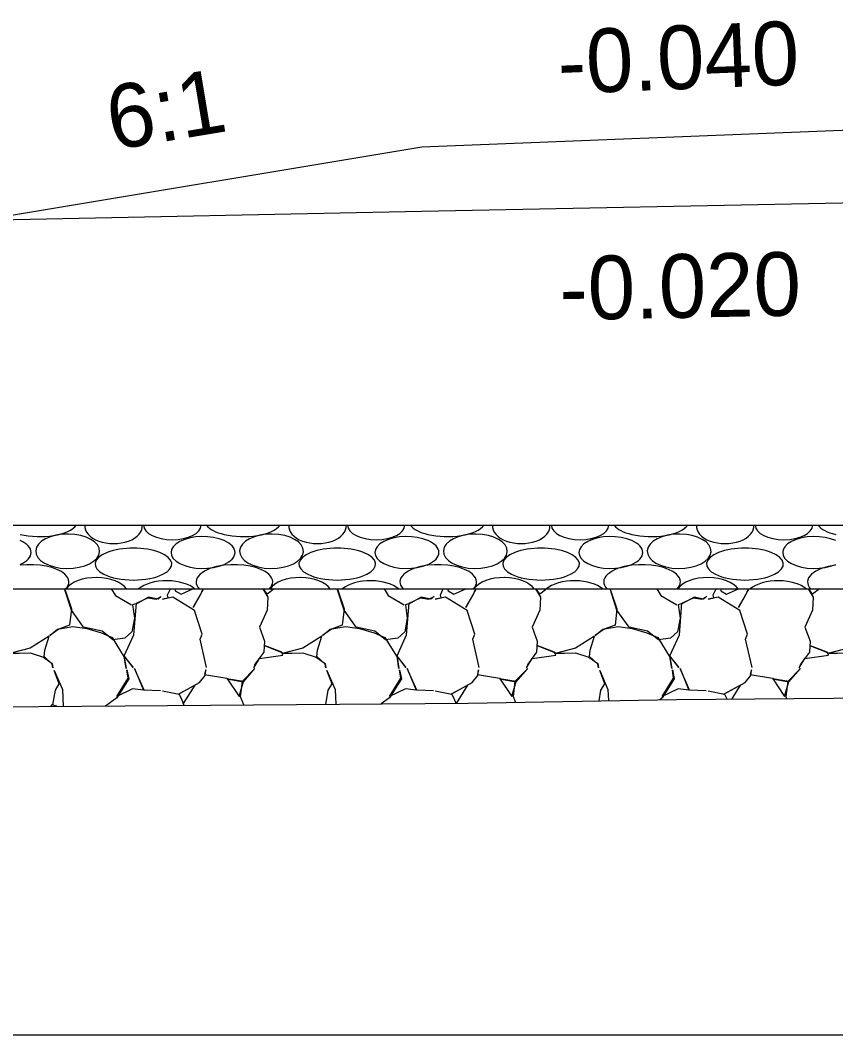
# Model space of a CAD drawing. Extents: x -26 to 4781, y -31 to 24738.
# Drawn here: x 2271.7 to 2284.49, y 14500 to 14515.93 of the extents above; entities that cross this region are included whole.
import ezdxf

# ---------------------------------------------------------------- set-up
doc = ezdxf.new("R2010")
doc.units = 0
for name, color, linetype in [('DESIGN - SHEET - Light Grid', 7, 'Continuous'), ('DESIGN - TRANSPORTATION - Proposed Layout Patterning', 7, 'Continuous'), ('DESIGN - TYPICAL - Finished Grade and Subgrade', 7, 'Continuous'), ('DESIGN - TYPICAL - Finished Grade Slopes Text', 7, 'Continuous'), ('DESIGN - TYPICAL - Subgrade Cross Slope Text', 7, 'Continuous'), ('GEOTECHNICAL – SCRATCH – Level 1', 7, 'Continuous'), ('SURVEY - GROUND - Top of Ground', 7, 'Continuous')]:
    doc.layers.add(name, color=color, linetype=linetype)

msp = doc.modelspace()

# ---------------------------------------------------------------- linework, layer by layer
at = {"layer": 'DESIGN - SHEET - Light Grid'}
msp.add_line((2000, 14500), (2300, 14500), dxfattribs=at)
at = {"layer": 'DESIGN - TRANSPORTATION - Proposed Layout Patterning'}
for points in [[(2271.224, 14507), (2271.301, 14506.869), (2271.291, 14506.669), (2271.171, 14506.399), (2271.251, 14506.179), (2271.241, 14506.009), (2271.101, 14505.819), (2271.081, 14505.759), (2271.171, 14505.909), (2271.541, 14505.959), (2271.521, 14506.009), (2271.261, 14506.109), (2271.551, 14505.989), (2271.681, 14505.989), (2271.851, 14505.999), (2272.061, 14505.929), (2272.201, 14505.829), (2272.211, 14505.759), (2272.201, 14505.819), (2272.071, 14505.939), (2272.081, 14506.039), (2272.151, 14506.259), (2271.851, 14506.069), (2271.551, 14505.989)], [(2272.383, 14507), (2272.401, 14506.979), (2272.501, 14506.689), (2272.471, 14506.429), (2272.301, 14506.369), (2272.161, 14506.269), (2272.281, 14506.369), (2272.521, 14506.409), (2272.741, 14506.379), (2272.971, 14506.309), (2273.141, 14506.239), (2273.331, 14505.929), (2273.361, 14505.749), (2273.331, 14505.939), (2273.471, 14505.769), (2273.331, 14505.949), (2273.481, 14506.279), (2273.521, 14506.779), (2273.701, 14506.859), (2273.831, 14506.839), (2273.911, 14506.879), (2273.861, 14506.839), (2273.711, 14506.869), (2273.541, 14506.779), (2273.461, 14506.749), (2273.491, 14506.539), (2273.451, 14506.329), (2273.341, 14506.229), (2273.151, 14506.199), (2272.981, 14506.339), (2272.691, 14506.399), (2272.501, 14506.669), (2272.393, 14507)], [(2273.127, 14507), (2273.191, 14506.899), (2273.441, 14506.749)], [(2274.621, 14505.769), (2274.521, 14506.209), (2274.551, 14506.289), (2274.431, 14506.659), (2274.091, 14506.869), (2273.931, 14506.839), (2274.021, 14506.859), (2274.011, 14506.909), (2274.056, 14507)], [(2274.125, 14507), (2274.131, 14506.969), (2274.221, 14506.919), (2274.408, 14507)], [(2274.573, 14507), (2274.521, 14506.909), (2274.411, 14506.709), (2274.521, 14506.899), (2274.568, 14507)], [(2275.504, 14507), (2275.581, 14506.869), (2275.571, 14506.669), (2275.451, 14506.399), (2275.531, 14506.179), (2275.521, 14506.009), (2275.381, 14505.819), (2275.361, 14505.759), (2275.451, 14505.909), (2275.821, 14505.959), (2275.801, 14506.009), (2275.541, 14506.109), (2275.831, 14505.989), (2275.961, 14505.989), (2276.131, 14505.999), (2276.341, 14505.929), (2276.481, 14505.829), (2276.491, 14505.759), (2276.481, 14505.819), (2276.351, 14505.939), (2276.361, 14506.039), (2276.431, 14506.259), (2276.131, 14506.069), (2275.831, 14505.989)], [(2275.68, 14507), (2275.571, 14506.919), (2275.515, 14507)], [(2276.663, 14507), (2276.681, 14506.979), (2276.781, 14506.689), (2276.751, 14506.429), (2276.581, 14506.369), (2276.441, 14506.269), (2276.561, 14506.369), (2276.801, 14506.409), (2277.021, 14506.379), (2277.251, 14506.309), (2277.421, 14506.239), (2277.611, 14505.929), (2277.641, 14505.749), (2277.611, 14505.939), (2277.751, 14505.769), (2277.611, 14505.949), (2277.761, 14506.279), (2277.801, 14506.779), (2277.981, 14506.859), (2278.111, 14506.839), (2278.191, 14506.879), (2278.141, 14506.839), (2277.991, 14506.869), (2277.821, 14506.779), (2277.741, 14506.749), (2277.771, 14506.539), (2277.731, 14506.329), (2277.621, 14506.229), (2277.431, 14506.199), (2277.261, 14506.339), (2276.971, 14506.399), (2276.781, 14506.669), (2276.673, 14507)], [(2277.407, 14507), (2277.471, 14506.899), (2277.721, 14506.749)], [(2278.901, 14505.769), (2278.801, 14506.209), (2278.831, 14506.289), (2278.711, 14506.659), (2278.371, 14506.869), (2278.211, 14506.839), (2278.301, 14506.859), (2278.291, 14506.909), (2278.336, 14507)], [(2278.405, 14507), (2278.411, 14506.969), (2278.501, 14506.919), (2278.688, 14507)], [(2278.853, 14507), (2278.801, 14506.909), (2278.691, 14506.709), (2278.801, 14506.899), (2278.848, 14507)], [(2279.784, 14507), (2279.861, 14506.869), (2279.851, 14506.669), (2279.731, 14506.399), (2279.811, 14506.179), (2279.801, 14506.009), (2279.661, 14505.819), (2279.641, 14505.759), (2279.731, 14505.909), (2280.101, 14505.959), (2280.081, 14506.009), (2279.821, 14506.109), (2280.111, 14505.989), (2280.241, 14505.989), (2280.411, 14505.999), (2280.621, 14505.929), (2280.761, 14505.829), (2280.771, 14505.759), (2280.761, 14505.819), (2280.631, 14505.939), (2280.641, 14506.039), (2280.711, 14506.259), (2280.411, 14506.069), (2280.111, 14505.989)], [(2279.96, 14507), (2279.851, 14506.919), (2279.795, 14507)], [(2280.943, 14507), (2280.961, 14506.979), (2281.061, 14506.689), (2281.031, 14506.429), (2280.861, 14506.369), (2280.721, 14506.269), (2280.841, 14506.369), (2281.081, 14506.409), (2281.301, 14506.379), (2281.531, 14506.309), (2281.701, 14506.239), (2281.891, 14505.929), (2281.921, 14505.749), (2281.891, 14505.939), (2282.031, 14505.769), (2281.891, 14505.949), (2282.041, 14506.279), (2282.081, 14506.779), (2282.261, 14506.859), (2282.391, 14506.839), (2282.471, 14506.879), (2282.421, 14506.839), (2282.271, 14506.869), (2282.101, 14506.779), (2282.021, 14506.749), (2282.051, 14506.539), (2282.011, 14506.329), (2281.901, 14506.229), (2281.711, 14506.199), (2281.541, 14506.339), (2281.251, 14506.399), (2281.061, 14506.669), (2280.953, 14507)], [(2281.687, 14507), (2281.751, 14506.899), (2282.001, 14506.749)], [(2283.181, 14505.769), (2283.081, 14506.209), (2283.111, 14506.289), (2282.991, 14506.659), (2282.651, 14506.869), (2282.491, 14506.839), (2282.581, 14506.859), (2282.571, 14506.909), (2282.616, 14507)], [(2282.685, 14507), (2282.691, 14506.969), (2282.781, 14506.919), (2282.968, 14507)], [(2283.133, 14507), (2283.081, 14506.909), (2282.971, 14506.709), (2283.081, 14506.899), (2283.128, 14507)], [(2284.064, 14507), (2284.141, 14506.869), (2284.131, 14506.669), (2284.011, 14506.399), (2284.091, 14506.179), (2284.081, 14506.009), (2283.941, 14505.819), (2283.921, 14505.759), (2284.011, 14505.909), (2284.381, 14505.959), (2284.361, 14506.009), (2284.101, 14506.109), (2284.391, 14505.989), (2284.521, 14505.989), (2284.691, 14505.999), (2284.901, 14505.929), (2285.041, 14505.829), (2285.051, 14505.759), (2285.041, 14505.819), (2284.911, 14505.939), (2284.921, 14506.039), (2284.991, 14506.259), (2284.691, 14506.069), (2284.391, 14505.989)], [(2284.24, 14507), (2284.131, 14506.919), (2284.075, 14507)], [(2272.268, 14505.154), (2272.211, 14505.179), (2272.251, 14505.409), (2272.311, 14505.509), (2272.231, 14505.719), (2272.361, 14505.419), (2272.37, 14505.155)], [(2273.901, 14505.399), (2273.641, 14505.409), (2273.491, 14505.749), (2273.631, 14505.409), (2273.461, 14505.429), (2273.211, 14505.309), (2273.391, 14505.599), (2273.371, 14505.729), (2273.401, 14505.589), (2273.211, 14505.289), (2273.036, 14505.16)], [(2273.931, 14505.399), (2274.191, 14505.349), (2274.261, 14505.199), (2274.441, 14505.489), (2274.181, 14505.349), (2274.511, 14505.529), (2274.601, 14505.639), (2274.611, 14505.729), (2274.591, 14505.659), (2274.941, 14505.599), (2275.131, 14505.309), (2275.201, 14505.549), (2274.941, 14505.589), (2275.201, 14505.539), (2275.381, 14505.749), (2275.181, 14505.549), (2275.151, 14505.309), (2275.206, 14505.177)], [(2276.492, 14505.187), (2276.531, 14505.409), (2276.591, 14505.509), (2276.511, 14505.719), (2276.641, 14505.419), (2276.648, 14505.189)], [(2278.181, 14505.399), (2277.921, 14505.409), (2277.771, 14505.749), (2277.911, 14505.409), (2277.741, 14505.429), (2277.491, 14505.309), (2277.671, 14505.599), (2277.651, 14505.729), (2277.681, 14505.589), (2277.491, 14505.289), (2277.362, 14505.194)], [(2278.543, 14505.203), (2278.721, 14505.489), (2278.461, 14505.349), (2278.791, 14505.529), (2278.881, 14505.639), (2278.891, 14505.729), (2278.871, 14505.659), (2279.221, 14505.599), (2279.411, 14505.309), (2279.481, 14505.549), (2279.221, 14505.589), (2279.481, 14505.539), (2279.661, 14505.749), (2279.461, 14505.549), (2279.431, 14505.309), (2279.469, 14505.219)], [(2280.782, 14505.243), (2280.811, 14505.409), (2280.871, 14505.509), (2280.791, 14505.719), (2280.921, 14505.419), (2280.927, 14505.246)], [(2282.461, 14505.399), (2282.201, 14505.409), (2282.051, 14505.749), (2282.191, 14505.409), (2282.021, 14505.429), (2281.771, 14505.309), (2281.951, 14505.599), (2281.931, 14505.729), (2281.961, 14505.589), (2281.771, 14505.289), (2281.733, 14505.261)], [(2282.867, 14505.274), (2283.001, 14505.489), (2282.741, 14505.349), (2283.071, 14505.529), (2283.161, 14505.639), (2283.171, 14505.729), (2283.151, 14505.659), (2283.501, 14505.599), (2283.691, 14505.309), (2283.761, 14505.549), (2283.501, 14505.589), (2283.761, 14505.539), (2283.941, 14505.749), (2283.741, 14505.549), (2283.711, 14505.309), (2283.722, 14505.281)], [(2278.211, 14505.399), (2278.471, 14505.349), (2278.538, 14505.203)], [(2282.491, 14505.399), (2282.751, 14505.349), (2282.786, 14505.273)], [(2272.266, 14505.154), (2272.271, 14505.159), (2272.191, 14505.179), (2272.173, 14505.154)], [(2274.27, 14505.17), (2274.251, 14505.209), (2274.269, 14505.17)], [(2278.533, 14505.203), (2278.531, 14505.209), (2278.533, 14505.203)]]:
    msp.add_lwpolyline(points, dxfattribs=at)
for centre, major_axis, ratio, start_param, end_param in [((2272, 14508.073), (-0.602, 0), 0.416667, 1.047185, 2.846662), ((2273.163, 14507.983), (-0.451, 0), 0.6, 6.21895, 9.489014), ((2274.085, 14508.003), (-0.451, 0), 0.511111, 0.011602, 3.129991), ((2275.198, 14508.073), (-0.602, 0), 0.416667, 0.29493, 1.047185), ((2275.199, 14508.073), (-0.602, 0), 0.416667, 1.047185, 2.846662), ((2276.362, 14507.983), (-0.451, 0), 0.6, 6.21895, 9.489014), ((2277.284, 14508.003), (-0.451, 0), 0.511111, 0.011602, 3.129991), ((2278.397, 14508.073), (-0.602, 0), 0.416667, 0.29493, 1.047185), ((2278.397, 14508.073), (-0.602, 0), 0.416667, 1.047185, 2.846662), ((2279.56, 14507.983), (-0.451, 0), 0.6, 6.21895, 9.489014), ((2280.483, 14508.003), (-0.451, 0), 0.511111, 0.011602, 3.129991), ((2281.596, 14508.073), (-0.602, 0), 0.416667, 0.29493, 1.047185), ((2281.596, 14508.073), (-0.602, 0), 0.416667, 1.047185, 2.846662), ((2282.759, 14507.983), (-0.451, 0), 0.6, 6.21895, 9.489014), ((2283.682, 14508.003), (-0.451, 0), 0.511111, 0.011602, 3.129991), ((2284.795, 14508.073), (-0.602, 0), 0.416667, 0.29493, 1.047185), ((2271.368, 14507.572), (-0.501, 0), 0.5, 2.292187, 3.991263), ((2272.441, 14507.592), (-0.501, 0), 0.54, 1.545388, 7.825415), ((2274.566, 14507.572), (-0.501, 0), 0.5, 3.991263, 8.575372), ((2274.567, 14507.572), (-0.501, 0), 0.5, 2.292187, 3.991263), ((2275.64, 14507.592), (-0.501, 0), 0.54, 1.545388, 7.825415), ((2277.765, 14507.572), (-0.501, 0), 0.5, 3.991263, 8.575372), ((2277.766, 14507.572), (-0.501, 0), 0.5, 2.292187, 3.991263), ((2278.839, 14507.592), (-0.501, 0), 0.54, 1.545388, 7.825415), ((2280.964, 14507.572), (-0.501, 0), 0.5, 3.991263, 8.575372), ((2280.965, 14507.572), (-0.501, 0), 0.5, 2.292187, 3.991263), ((2282.037, 14507.592), (-0.501, 0), 0.54, 1.545388, 7.825415), ((2284.163, 14507.572), (-0.501, 0), 0.5, 3.991263, 8.575372), ((2273.474, 14507.391), (-0.602, 0), 0.416667, 2.446, 6.978671), ((2276.672, 14507.391), (-0.602, 0), 0.416667, 2.446, 6.978671), ((2279.871, 14507.391), (-0.602, 0), 0.416667, 2.446, 6.978671), ((2283.07, 14507.391), (-0.602, 0), 0.416667, 2.446, 6.978671), ((2271.859, 14507.11), (-0.602, 0), 0.45, 3.602876, 4.982641), ((2275.058, 14507.11), (-0.602, 0), 0.45, 4.982641, 5.821976), ((2275.058, 14507.11), (-0.602, 0), 0.45, 3.602876, 4.982641), ((2278.257, 14507.11), (-0.602, 0), 0.45, 4.982641, 5.821976), ((2278.257, 14507.11), (-0.602, 0), 0.45, 3.602876, 4.982641), ((2281.455, 14507.11), (-0.602, 0), 0.45, 4.982641, 5.821976), ((2281.456, 14507.11), (-0.602, 0), 0.45, 3.602876, 4.982641), ((2284.654, 14507.11), (-0.602, 0), 0.45, 4.982641, 5.821976), ((2271.859, 14507.11), (-0.602, 0), 0.45, 2.723371, 3.602877), ((2272.892, 14506.909), (-0.501, 0), 0.54, 4.698848, 5.942), ((2272.892, 14506.909), (-0.501, 0), 0.54, 3.482778, 4.691622), ((2273.474, 14507.391), (-0.602, 0), 0.416667, 0.695486, 2.446), ((2273.995, 14506.879), (-0.501, 0), 0.5, 4.691313, 5.780965), ((2273.995, 14506.879), (-0.501, 0), 0.5, 3.643813, 4.683059), ((2275.058, 14507.11), (-0.602, 0), 0.45, 5.821976, 6.701407), ((2275.058, 14507.11), (-0.602, 0), 0.45, 2.723371, 3.602877), ((2276.091, 14506.909), (-0.501, 0), 0.54, 4.698848, 5.942), ((2276.091, 14506.909), (-0.501, 0), 0.54, 3.482778, 4.691622), ((2276.672, 14507.391), (-0.602, 0), 0.416667, 0.695486, 2.446), ((2277.194, 14506.879), (-0.501, 0), 0.5, 4.691313, 5.780965), ((2277.194, 14506.879), (-0.501, 0), 0.5, 3.643813, 4.683059), ((2278.257, 14507.11), (-0.602, 0), 0.45, 5.821976, 6.701407), ((2278.257, 14507.11), (-0.602, 0), 0.45, 2.723371, 3.602877), ((2279.29, 14506.909), (-0.501, 0), 0.54, 4.698848, 5.942), ((2279.29, 14506.909), (-0.501, 0), 0.54, 3.482778, 4.691622), ((2279.871, 14507.391), (-0.602, 0), 0.416667, 0.695486, 2.446), ((2280.393, 14506.879), (-0.501, 0), 0.5, 4.691313, 5.780965), ((2280.393, 14506.879), (-0.501, 0), 0.5, 3.643813, 4.683059), ((2281.455, 14507.11), (-0.602, 0), 0.45, 5.821976, 6.701407), ((2281.456, 14507.11), (-0.602, 0), 0.45, 2.723371, 3.602877), ((2282.489, 14506.909), (-0.501, 0), 0.54, 4.698848, 5.942), ((2282.489, 14506.909), (-0.501, 0), 0.54, 3.482778, 4.691622), ((2283.07, 14507.391), (-0.602, 0), 0.416667, 0.695486, 2.446), ((2283.592, 14506.879), (-0.501, 0), 0.5, 4.691313, 5.780965), ((2283.592, 14506.879), (-0.501, 0), 0.5, 3.643813, 4.683059), ((2284.654, 14507.11), (-0.602, 0), 0.45, 5.821976, 6.701407)]:
    msp.add_ellipse(centre, major_axis=major_axis, ratio=ratio, start_param=start_param, end_param=end_param, dxfattribs=at)
at = {"layer": 'DESIGN - TYPICAL - Finished Grade and Subgrade'}
for p, q in [((2288, 14514.336), (2278, 14513.936)), ((2278, 14513.936), (2271.114, 14512.789)), ((2288, 14513.126), (2278, 14512.926)), ((2278, 14512.926), (2271.114, 14512.789))]:
    msp.add_line(p, q, dxfattribs=at)
at = {"layer": 'GEOTECHNICAL – SCRATCH – Level 1'}
for p, q in [((2256.747, 14508), (2315.729, 14508)), ((2253.747, 14507), (2309.399, 14507))]:
    msp.add_line(p, q, dxfattribs=at)
at = {"layer": 'SURVEY - GROUND - Top of Ground'}
msp.add_lwpolyline([(2240.18, 14503.958), (2250.843, 14504.763), (2255.374, 14504.984), (2259.845, 14505.115), (2264.597, 14505.101), (2268.614, 14505.126), (2278.725, 14505.205), (2281.994, 14505.266), (2290, 14505.333), (2290.47, 14505.374), (2300, 14506.289), (2302.911, 14506.568), (2306.66, 14506.76), (2310.416, 14507.089), (2317.187, 14508.25), (2321.277, 14508.836)], dxfattribs=at)

# ---------------------------------------------------------------- texts
at = {"layer": 'DESIGN - TYPICAL - Finished Grade Slopes Text'}
for s, rotation, p in [('-0.040', 2.2906, (2280.149, 14514.772)), ('6:1', 9.4623, (2273.145, 14513.888))]:
    msp.add_text(s, height=1, rotation=rotation, dxfattribs=at).set_placement(p)
at = {"layer": 'DESIGN - TYPICAL - Subgrade Cross Slope Text'}
msp.add_text('-0.020', height=1, rotation=1.1458, dxfattribs=at).set_placement((2280.167, 14511.22))

doc.saveas('drawing.dxf')
